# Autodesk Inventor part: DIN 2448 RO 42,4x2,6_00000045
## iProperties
Created: 2006-03
Part Number: DIN 2448 RO 42,4x2,6_00000045
Material: Default
Document SubType Name: Modeling
Designer: Carlo
Stock Number: DIN 2448 RO 42,4x2,6
Mass: 666.432 g
Surface Area: 5139.94 cm^2
Volume: 666.432 cm^3
Density: 1 g/cm^3
G_L: 2080.000 mm
G_W: 42.400 mm
G_H: 42.400 mm
AFG_Item: 42.4 x 2.6
CSToolsMass: 1.0
CSToolsVolume: 666432.0
CSToolsArea: 5140.0
Author: Carlo
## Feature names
1. AFG_Detailed_DIN 2448 RO 42,4x2,6_00000045 [Extrusion]
2. AFG_Simplified_DIN 2448 RO 42,4x2,6_00000045 [Extrusion]
3. AFG_EndExtrusion_1 [Extrusion]
4. AFG_EndExtrusion_2 [Extrusion]
5. AFG_StartExtrusion_1 [Extrusion]
6. AFG_StartExtrusion_2 [Extrusion]
